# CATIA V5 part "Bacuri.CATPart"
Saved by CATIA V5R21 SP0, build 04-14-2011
Part number: Bacuri
Bounding box of the stored display mesh (mm): x -17 to 17, y 135 to 225, z -31.5 to 89
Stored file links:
  C:\Users\MIRCEA\Desktop\PRRO\CATIAV5\Bacuri.CATPart
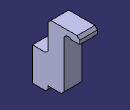
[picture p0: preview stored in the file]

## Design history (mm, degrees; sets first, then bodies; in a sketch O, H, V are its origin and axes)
Body1 (main body)
  Plane1: type Offset, RefPlane zx-plane, Offset 165
  Plane2: type Offset, RefPlane zx-plane, Offset 135
  Sketch1 on Plane2, origin (0, 135, 0), H (-1, 0, 0), V (0, 0, 1)
    line L1 (17, 31.5) -> (17, -31.5)
    line L2 (17, -31.5) -> (-17, -31.5)
    line L3 (-17, -31.5) -> (-17, 31.5)
    line L4 (-17, 31.5) -> (17, 31.5)
    distance L2 L4 = 63
    distance L1 L3 = 34
    vertical: L1 V, L3 V
    horizontal: L2 H, L4 H
    equidistance: L1 L3 O, L2 L4 O
  Pad1: profile Sketch1, direction (0, 1, 0), length 30
  Sketch2 on Plane1, origin (0, 165, 0), H (-1, 0, 0), V (0, 0, 1)
    line L1 (17, 89) -> (-17, 89)
    line L2 (-17, 89) -> (-17, -21)
    line L3 (-17, -21) -> (17, -21)
    line L4 (17, 89) -> (17, -21)
    length L1 = 34
    length L2 = 110
    horizontal: L1 H, L3 H
    vertical: L2 V, L4 V
  Pad2: profile Sketch2, direction (0, 1, 0), length 30
  Plane3: type Offset, RefPlane Plane1, Offset 30
  Sketch3 on Plane3, origin (0, 195, 0), H (-1, 0, 0), V (0, 0, 1)
    line L1 (17, 89) -> (17, 79)
    line L2 (17, 79) -> (-17, 79)
    line L3 (-17, 79) -> (-17, 89)
    line L4 (17, 89) -> (-17, 89)
    length L1 = 10
    length L2 = 34
    vertical: L1 V, L3 V
    horizontal: L2 H, L4 H
  Pad3: profile Sketch3, direction (0, 1, 0), length 30
  Chamfer1: length 5, angle 45, on edge [start face of Pad2 | face of Pad3]; edge [face of Pad2 from Sketch2.L3 | end face of Pad2]; edge [face of Pad1 from Sketch1.L2 | end face of Pad1]
  Chamfer2: length 5, angle 45, on edge [end face of Pad2 | face of Pad3 from Sketch3.L2]; edge [face of Pad1 from Sketch1.L4 | start face of Pad2]
  Sketch4 on face of Pad3 from Sketch3.L2, origin (0, 0, 79), H (1, 0, 0), V (0, -1, 0)
    line L1 (17, -225) -> (17, -208)
    line L2 (17, -225) -> (-17, -225)
    line L3 (17, -208) -> (-17, -208)
    line L4 (-17, -208) -> (-17, -225)
    length L1 = 17
    length L2 = 34
    vertical: L1 V, L4 V
    horizontal: L2 H, L3 H
  Pad4: profile Sketch4, direction (0, 0, -1), length 2.2
  Chamfer3: length 5, angle 45, on edge [face of Pad3 | face of Pad4]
